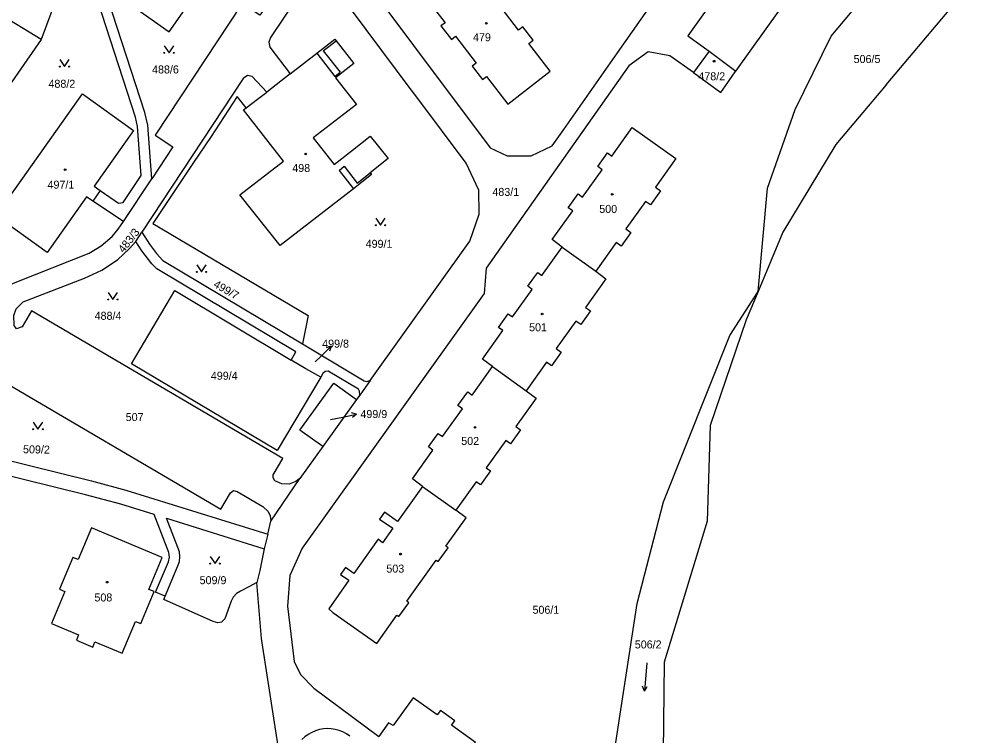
# Model space of a CAD drawing. Extents: x -558358 to -557517, y -1073786 to -1073189.
# Drawn here: x -558018.3 to -557815.7, y -1073559.5 to -1073407.2 of the extents above; entities that cross this region are included whole.
import ezdxf

# ---------------------------------------------------------------- set-up
doc = ezdxf.new("R2010")
doc.units = 0
for name, color, linetype in [('Hranice parcel', 7, 'Continuous'), ('Parcelní čísla', 7, 'Continuous'), ('Pop  PČ popisy', 7, 'Continuous'), ('Vnitřní kresba', 7, 'Continuous'), ('Značky budov', 7, 'Continuous'), ('Značky kultur', 7, 'Continuous')]:
    doc.layers.add(name, color=color, linetype=linetype)

msp = doc.modelspace()

# ---------------------------------------------------------------- linework, layer by layer
at = {"layer": 'Hranice parcel'}
for p, q in [((-557834.15, -1073421.11), (-557815.73, -1073399.27)), ((-558013.61, -1073411.49), (-558024.42, -1073404.91)), ((-558013.61, -1073411.49), (-558027.22, -1073431.17)), ((-557965.04, -1073413.14), (-557960.73, -1073418.81)), ((-557871.76, -1073413.96), (-557875.08, -1073418.52)), ((-557871.76, -1073413.96), (-557866.06, -1073418.25)), ((-557965.67, -1073422.67), (-557968.81, -1073419.39)), ((-557960.73, -1073418.81), (-557965.67, -1073422.67)), ((-557970.03, -1073426.04), (-557971.99, -1073423.64)), ((-557996.12, -1073450.19), (-557990.11, -1073441.11)), ((-558001.05, -1073443.62), (-558002.62, -1073445.83)), ((-558001.05, -1073443.62), (-557997.16, -1073446.28)), ((-557996.12, -1073450.19), (-558002.62, -1073445.83)), ((-557993.5, -1073454.4), (-557992.19, -1073452.45)), ((-557902.93, -1073455.63), (-557895.8, -1073460.74)), ((-557987.76, -1073458.45), (-557958.11, -1073476.19)), ((-557958.11, -1073476.19), (-557944.96, -1073484.06)), ((-557917.76, -1073481.02), (-557910.62, -1073486.13)), ((-557958.62, -1073494.5), (-557951.44, -1073484.51)), ((-557951.44, -1073484.51), (-557946.6, -1073487.99)), ((-557943.74, -1073483.99), (-557945.94, -1073487.07)), ((-557944.96, -1073484.06), (-557944.51, -1073484.17)), ((-557944.51, -1073484.17), (-557943.74, -1073483.99)), ((-557945.94, -1073487.07), (-557946.6, -1073487.99)), ((-557945.94, -1073487.07), (-557945.95, -1073486.25)), ((-557946.6, -1073487.99), (-557953.75, -1073497.99)), ((-557953.75, -1073497.99), (-557958.62, -1073494.5)), ((-557953.75, -1073497.99), (-557958.67, -1073504.77)), ((-557964.79, -1073513.87), (-557958.67, -1073504.77)), ((-557932.61, -1073506.45), (-557925.51, -1073511.53)), ((-557965.43, -1073516.64), (-557964.79, -1073513.87)), ((-557872.13, -1073513.82), (-557881.3, -1073543.83)), ((-557965.43, -1073516.64), (-557966.22, -1073519.7)), ((-557966.22, -1073519.7), (-557967.17, -1073524.31)), ((-557967.17, -1073524.31), (-557967.76, -1073526.9)), ((-557967.76, -1073526.9), (-557969.49, -1073527.78))]:
    msp.add_line(p, q, dxfattribs=at)
for points in [[(-558022.09, -1073311.21), (-558020.08, -1073313.87), (-558000.41, -1073328.2), (-557993.92, -1073334.5), (-557986.04, -1073343.93), (-557967.1, -1073369.2), (-557918.24, -1073434.51), (-557914.64, -1073436.24), (-557909.55, -1073436.22), (-557905.05, -1073434.1), (-557902.57, -1073430.65), (-557891.22, -1073414.37), (-557877.97, -1073395.43)], [(-557997.16, -1073446.28), (-557996.18, -1073446.14), (-557992.37, -1073440.37), (-557993.13, -1073429.99), (-557993.58, -1073428.02), (-558004.25, -1073395), (-558005.55, -1073391.58), (-558006.57, -1073389.94), (-558009.69, -1073386.81), (-558015.69, -1073381.13), (-558022.86, -1073375.1), (-558038.38, -1073364.54), (-558051.46, -1073355.75)], [(-557845.99, -1073372.93), (-557859.12, -1073391.15), (-557861.27, -1073389.6), (-557876.27, -1073410.74), (-557871.76, -1073413.96)], [(-557866.06, -1073418.25), (-557853.54, -1073400.64), (-557853.96, -1073400.34), (-557838.68, -1073378.19)], [(-558011.29, -1073387.48), (-558006.6, -1073392.58), (-558013.61, -1073411.49)], [(-557861.36, -1073465.07), (-557859.38, -1073443.12), (-557853.44, -1073426.35), (-557845.8, -1073410.81), (-557826.12, -1073387.26)], [(-557930.26, -1073400.48), (-557932.35, -1073402.1), (-557927.81, -1073407.96), (-557928.68, -1073408.63), (-557926.46, -1073411.51), (-557925.59, -1073410.83), (-557921.19, -1073416.52), (-557922.06, -1073417.2), (-557919.87, -1073420.02), (-557919, -1073419.35), (-557914.46, -1073425.22), (-557905.47, -1073418.2), (-557910.01, -1073412.34), (-557909.08, -1073411.62), (-557911.27, -1073408.79), (-557912.2, -1073409.51), (-557916.62, -1073403.8), (-557915.7, -1073403.08), (-557917.89, -1073400.24), (-557918.82, -1073400.96), (-557923.37, -1073395.09)], [(-557990.11, -1073441.11), (-557990.95, -1073429.72), (-557991.6, -1073426.99), (-558000.34, -1073399.97), (-557986.42, -1073409.86), (-557979.13, -1073399.38), (-557977.23, -1073400.7), (-557975.75, -1073398.59), (-557966.19, -1073404.96)], [(-557952.73, -1073399.73), (-557953.94, -1073399.59), (-557955.93, -1073399.82), (-557957.72, -1073400.8), (-557958.97, -1073402.15), (-557964.89, -1073411.09), (-557965.23, -1073412.1), (-557965.04, -1073413.14)], [(-557943.74, -1073483.99), (-557922.57, -1073454.37), (-557920.54, -1073448.62), (-557920.67, -1073443.5), (-557923.32, -1073437.76), (-557933.57, -1073424.07), (-557935, -1073422.19), (-557950.81, -1073400.97)], [(-557966.19, -1073404.96), (-557967.15, -1073406.3), (-557970.9, -1073403.86), (-557989.34, -1073431.82), (-557985.62, -1073434.28), (-557990.11, -1073441.11)], [(-557960.73, -1073418.81), (-557955.07, -1073414.41), (-557951.22, -1073411.42), (-557950.93, -1073411.8), (-557947.21, -1073416.59), (-557951.08, -1073419.63), (-557946.63, -1073425.3), (-557955.8, -1073432.39), (-557951.37, -1073438.08), (-557947.44, -1073435.04), (-557943.73, -1073432.04), (-557939.89, -1073436.78), (-557943.7, -1073439.86), (-557943.42, -1073440.21), (-557947.29, -1073443.23), (-557962.81, -1073455.3), (-557971.36, -1073444.52), (-557962.13, -1073437.38), (-557970.6, -1073426.47), (-557970.03, -1073426.04)], [(-557875.08, -1073418.52), (-557880.11, -1073415), (-557884.66, -1073414.11), (-557888.78, -1073417.07), (-557919.08, -1073460.09), (-557919.51, -1073465.45), (-557958.15, -1073519.56), (-557960.76, -1073525.37), (-557961.25, -1073531.9), (-557959.85, -1073543.64), (-557958.52, -1073546.41), (-557955.67, -1073549.33), (-557941.9, -1073559.58)], [(-557875.08, -1073418.52), (-557869.25, -1073422.74), (-557867.79, -1073420.61), (-557866.54, -1073418.89), (-557866.06, -1073418.25)], [(-557968.81, -1073419.39), (-557969.8, -1073419.14), (-557970.66, -1073419.77), (-557992.19, -1073452.45)], [(-557970.03, -1073426.04), (-557967.63, -1073424.2), (-557965.67, -1073422.67)], [(-557834.15, -1073421.11), (-557844.86, -1073433.81), (-557856.07, -1073452.41), (-557861.36, -1073465.07)], [(-558023.22, -1073448.98), (-558004.82, -1073423.06), (-557993.94, -1073430.83), (-558002.36, -1073442.69), (-558001.05, -1073443.62)], [(-557971.99, -1073423.64), (-557977.49, -1073432.15), (-557981.25, -1073437.64), (-557989.89, -1073450.63)], [(-557902.93, -1073455.63), (-557905.05, -1073454), (-557900.72, -1073447.94), (-557901.66, -1073447.27), (-557899.55, -1073444.33), (-557898.62, -1073444.99), (-557894.46, -1073439.18), (-557895.4, -1073438.51), (-557893.33, -1073435.61), (-557892.39, -1073436.28), (-557888.07, -1073430.23), (-557878.84, -1073436.82), (-557883.15, -1073442.9), (-557882.08, -1073443.65), (-557884.22, -1073446.66), (-557885.28, -1073445.91), (-557889.41, -1073451.73), (-557888.35, -1073452.48), (-557890.43, -1073455.41), (-557891.49, -1073454.66), (-557895.8, -1073460.74)], [(-558002.62, -1073445.83), (-558003.93, -1073444.91), (-558012.33, -1073456.75), (-558023.22, -1073448.98)], [(-558020.42, -1073463.73), (-558018.76, -1073463.03), (-558003.4, -1073456.89), (-558000.84, -1073455.32), (-557998.53, -1073453.34), (-557997.26, -1073451.83), (-557996.12, -1073450.19)], [(-557989.89, -1073450.63), (-557956.91, -1073470.13), (-557958.11, -1073476.19)], [(-557992.19, -1073452.45), (-557990.57, -1073454.98), (-557989.11, -1073456.98), (-557987.76, -1073458.45)], [(-558018.89, -1073468.72), (-558017.43, -1073467.28), (-558004.36, -1073462.2), (-558000.71, -1073460.54), (-557997.38, -1073458.33), (-557994.81, -1073455.9), (-557993.5, -1073454.4)], [(-557960.53, -1073479.61), (-557959.52, -1073477.88), (-557988.99, -1073460.22), (-557990.09, -1073459.14), (-557992.19, -1073456.42), (-557993.5, -1073454.4)], [(-557917.76, -1073481.02), (-557919.89, -1073479.42), (-557915.58, -1073473.37), (-557916.49, -1073472.72), (-557914.4, -1073469.79), (-557913.49, -1073470.44), (-557909.33, -1073464.6), (-557910.24, -1073463.95), (-557908.96, -1073462.17), (-557908.15, -1073461.02), (-557907.24, -1073461.67), (-557902.93, -1073455.63)], [(-557895.8, -1073460.74), (-557893.65, -1073462.39), (-557897.97, -1073468.43), (-557896.94, -1073469.17), (-557899.02, -1073472.08), (-557900.05, -1073471.34), (-557904.22, -1073477.17), (-557903.16, -1073477.93), (-557905.25, -1073480.84), (-557906.3, -1073480.09), (-557910.62, -1073486.13)], [(-557954.23, -1073483.22), (-557963.48, -1073498.87), (-557994.38, -1073480.4), (-557985.2, -1073464.81), (-557960.53, -1073479.61)], [(-557897.48, -1073592.57), (-557892.38, -1073566.43), (-557887.02, -1073531.37), (-557881.44, -1073509.74), (-557867.37, -1073474.4), (-557861.36, -1073465.07)], [(-557861.36, -1073465.07), (-557863.88, -1073471.1), (-557871.54, -1073493.51), (-557872.13, -1073513.82)], [(-557958.67, -1073504.77), (-557959.52, -1073505.42), (-557960.94, -1073505.97), (-557962.48, -1073505.9), (-557963.93, -1073505.3), (-557964.34, -1073504.64), (-557964.29, -1073503.98), (-557962.25, -1073500.52), (-558015.64, -1073469.14), (-558017.62, -1073472.56), (-558018.8, -1073472.98), (-558019.32, -1073472.29), (-558019.38, -1073470.18), (-558018.89, -1073468.72)], [(-558028.88, -1073478.68), (-558027.22, -1073477.58), (-558025.14, -1073477.37), (-558022.91, -1073477.77), (-558021.94, -1073478.27), (-558021.58, -1073478.9), (-558021.69, -1073479.54), (-558023.7, -1073482.95), (-557975.42, -1073511.29), (-557973.41, -1073507.84), (-557972.71, -1073507.36), (-557971.95, -1073507.53), (-557966.49, -1073510.72), (-557965.39, -1073511.77), (-557964.96, -1073512.7), (-557964.79, -1073513.87)], [(-557954.23, -1073483.22), (-557957.38, -1073481.46), (-557960.53, -1073479.61)], [(-557932.61, -1073506.45), (-557934.75, -1073504.84), (-557930.41, -1073498.76), (-557931.35, -1073498.09), (-557930.07, -1073496.31), (-557929.28, -1073495.19), (-557928.34, -1073495.86), (-557924.14, -1073489.96), (-557925.07, -1073489.3), (-557922.99, -1073486.39), (-557922.06, -1073487.05), (-557917.76, -1073481.02)], [(-557945.95, -1073486.25), (-557946.2, -1073485.81), (-557952.65, -1073481.96), (-557953.3, -1073482.07), (-557953.78, -1073482.47), (-557954.23, -1073483.22)], [(-557910.62, -1073486.13), (-557908.48, -1073487.72), (-557912.81, -1073493.77), (-557911.82, -1073494.47), (-557913.92, -1073497.39), (-557914.9, -1073496.69), (-557919.09, -1073502.55), (-557918.19, -1073503.19), (-557920.29, -1073506.11), (-557921.18, -1073505.47), (-557925.51, -1073511.53)], [(-558041.79, -1073496.35), (-558023.3, -1073500.28), (-558002.91, -1073505.27), (-557995.6, -1073507.26), (-557965.43, -1073516.64)], [(-557987.27, -1073529.77), (-557989.29, -1073528.94), (-557986.56, -1073522.48), (-557986.36, -1073521.52), (-557986.44, -1073520.51), (-557989.6, -1073512.4), (-557996.64, -1073510.25), (-558004.14, -1073508.22), (-558024.01, -1073503.35), (-558039.66, -1073500.03), (-558040.64, -1073500.03), (-558041.42, -1073500.4), (-558042.23, -1073501), (-558043.97, -1073502.01), (-558045.84, -1073502.74), (-558047.8, -1073503.22), (-558050.8, -1073503.37), (-558053.79, -1073503.03), (-558062.52, -1073500.9), (-558063.99, -1073500.68), (-558064.96, -1073500.91), (-558065.77, -1073501.48), (-558066.28, -1073502.33), (-558068.72, -1073511.63)], [(-557932.61, -1073506.45), (-557937.92, -1073513.94), (-557940.69, -1073511.97), (-557941.71, -1073513.4), (-557938.93, -1073515.37), (-557941.12, -1073518.46), (-557942.01, -1073517.7), (-557947.21, -1073524.97), (-557948.97, -1073523.73), (-557949.99, -1073525.17), (-557948.24, -1073526.41), (-557952.49, -1073532.47), (-557951.63, -1073533.27), (-557942.33, -1073539.86), (-557938.05, -1073533.83), (-557937.62, -1073534.14), (-557935.52, -1073531.19), (-557935.95, -1073530.88), (-557929.72, -1073522.11), (-557929.27, -1073522.43), (-557927.19, -1073519.5), (-557927.64, -1073519.19), (-557923.33, -1073513.13), (-557925.51, -1073511.53)], [(-557987.27, -1073529.77), (-557984.55, -1073523.36), (-557984.23, -1073522.42), (-557984.14, -1073521.45), (-557984.2, -1073520.39), (-557986.94, -1073513.23), (-557966.22, -1073519.7)], [(-558008.57, -1073528.8), (-558011.42, -1073535.59), (-558005.63, -1073538.02), (-558006.1, -1073539.13), (-558002.62, -1073540.59), (-558002.16, -1073539.49), (-557996.41, -1073541.91), (-557993.56, -1073535.14), (-557992.45, -1073535.6), (-557989.61, -1073528.81), (-557990.71, -1073528.34), (-557987.91, -1073521.54), (-558002.9, -1073515.24), (-558005.74, -1073522.02), (-558006.84, -1073521.56), (-558009.68, -1073528.33), (-558008.57, -1073528.8)], [(-557969.49, -1073527.78), (-557971.24, -1073528.71), (-557972.09, -1073529.24), (-557972.78, -1073529.97), (-557973.26, -1073530.86), (-557974.57, -1073534.63), (-557975.26, -1073535.31), (-557976.1, -1073535.45), (-557977.05, -1073535.17), (-557987.55, -1073530.47), (-557987.27, -1073529.77)], [(-557961.12, -1073576.24), (-557962.13, -1073568.62), (-557962.94, -1073563.5), (-557966.76, -1073538.79), (-557967.76, -1073526.9)], [(-557881.3, -1073543.83), (-557881.54, -1073569.39), (-557886.18, -1073582.51)], [(-557944.07, -1073562.64), (-557943.15, -1073563.3), (-557947.42, -1073569.28), (-557934.16, -1073578.7), (-557929.93, -1073572.77), (-557928.96, -1073573.46), (-557924.72, -1073567.52), (-557925.63, -1073566.74), (-557921.33, -1073560.9), (-557926.44, -1073557.23), (-557925.76, -1073556.27), (-557928.81, -1073554.08), (-557929.5, -1073555.03), (-557934.61, -1073551.36), (-557938.85, -1073557.29), (-557939.81, -1073556.68), (-557941.9, -1073559.58)], [(-557948.05, -1073559.56), (-557948.76, -1073559.06), (-557949.52, -1073558.64), (-557950.33, -1073558.32), (-557951.17, -1073558.09), (-557952.03, -1073557.96), (-557952.77, -1073557.92), (-557953.64, -1073557.97), (-557954.49, -1073558.12), (-557955.32, -1073558.37), (-557956.12, -1073558.72), (-557956.88, -1073559.15), (-557957.57, -1073559.67), (-557958.21, -1073560.26)]]:
    msp.add_lwpolyline(points, dxfattribs=at)
at = {"layer": 'Pop  PČ popisy'}
for p, q in [((-557954.15, -1073478.76), (-557951.99, -1073476.68)), ((-557951.99, -1073476.68), (-557953.06, -1073477.01)), ((-557951.99, -1073476.68), (-557952.36, -1073477.73)), ((-557955.41, -1073479.99), (-557954.15, -1073478.76)), ((-557949.53, -1073491.73), (-557946.59, -1073491.11)), ((-557946.59, -1073491.11), (-557947.68, -1073490.82)), ((-557946.59, -1073491.11), (-557947.47, -1073491.8)), ((-557952.15, -1073492.28), (-557949.53, -1073491.73))]:
    msp.add_line(p, q, dxfattribs=at)
at = {"layer": 'Vnitřní kresba'}
for p, q in [((-557953.7, -1073413.91), (-557950.93, -1073411.8)), ((-557955.07, -1073414.41), (-557951.25, -1073419.34)), ((-557953.7, -1073413.91), (-557950.12, -1073418.46)), ((-557951.25, -1073419.34), (-557950.12, -1073418.46)), ((-557950.33, -1073439.32), (-557949.26, -1073438.42)), ((-557949.26, -1073438.42), (-557946.5, -1073442)), ((-557950.33, -1073439.32), (-557947.29, -1073443.23)), ((-557946.5, -1073442), (-557943.7, -1073439.86))]:
    msp.add_line(p, q, dxfattribs=at)
at = {"layer": 'Značky budov'}
for centre in [(-557919.07, -1073408.06), (-557870.69, -1073416.12), (-557957.4, -1073435.82), (-558008.5, -1073439.16), (-557892.32, -1073444.4), (-557907.2, -1073469.84), (-557921.47, -1073493.92), (-557937.27, -1073520.85), (-557999.58, -1073526.81)]:
    msp.add_circle(centre, 0.175, dxfattribs=at)
at = {"layer": 'Značky kultur'}
for p, q in [((-557884.95, -1073543.96), (-557885.47, -1073549.94)), ((-557885.47, -1073549.94), (-557885.89, -1073548.92)), ((-557885.47, -1073549.94), (-557884.89, -1073549.01))]:
    msp.add_line(p, q, dxfattribs=at)
for points in [[(-557987.43, -1073412.84), (-557986.43, -1073414.34), (-557985.43, -1073412.84)], [(-558009.6, -1073415.75), (-558008.6, -1073417.25), (-558007.6, -1073415.75)], [(-557942.51, -1073449.49), (-557941.51, -1073450.99), (-557940.51, -1073449.49)], [(-557980.53, -1073459.39), (-557979.53, -1073460.89), (-557978.53, -1073459.39)], [(-557999.34, -1073465.25), (-557998.34, -1073466.75), (-557997.34, -1073465.25)], [(-558015.26, -1073492.81), (-558014.26, -1073494.31), (-558013.26, -1073492.81)], [(-557977.66, -1073521.36), (-557976.66, -1073522.86), (-557975.66, -1073521.36)]]:
    msp.add_lwpolyline(points, dxfattribs=at)
for centre in [(-557987.43, -1073414.34), (-557985.43, -1073414.34), (-558009.6, -1073417.25), (-558007.6, -1073417.25), (-557942.51, -1073450.99), (-557940.51, -1073450.99), (-557980.53, -1073460.89), (-557978.53, -1073460.89), (-557999.34, -1073466.75), (-557997.34, -1073466.75), (-558015.26, -1073494.31), (-558013.26, -1073494.31), (-557977.66, -1073522.86), (-557975.66, -1073522.86)]:
    msp.add_circle(centre, 0.1, dxfattribs=at)

# ---------------------------------------------------------------- texts
at = {"layer": 'Parcelní čísla'}
for s, p in [('479', (-557921.88, -1073411.88)), ('506/5', (-557841.06, -1073416.5)), ('488/6', (-557990.03, -1073418.72)), ('478/2', (-557874.03, -1073420.17)), ('488/2', (-558012.03, -1073421.76)), ('498', (-557960.26, -1073439.66)), ('497/1', (-558012.23, -1073443.2)), ('483/1', (-557917.77, -1073444.74)), ('500', (-557895.07, -1073448.35)), ('499/1', (-557944.68, -1073455.77)), ('488/4', (-558002.23, -1073471.06)), ('501', (-557909.97, -1073473.5)), ('499/8', (-557953.91, -1073476.98)), ('499/4', (-557977.55, -1073483.8)), ('507', (-557995.63, -1073492.58)), ('499/9', (-557945.79, -1073491.94)), ('502', (-557924.38, -1073497.65)), ('503', (-557940.28, -1073524.78)), ('509/9', (-557979.93, -1073527.24)), ('508', (-558002.27, -1073530.91)), ('506/1', (-557909.25, -1073533.53)), ('506/2', (-557887.53, -1073540.89))]:
    msp.add_text(s, height=1.7, dxfattribs=at).set_placement(p)
for s, rotation, p in [('483/3', 52, (-557996.07, -1073456.97)), ('499/7', 330, (-557977.15, -1073463.99)), ('509/2', 359, (-558017.44, -1073499.41))]:
    msp.add_text(s, height=1.7, rotation=rotation, dxfattribs=at).set_placement(p)

doc.saveas('drawing.dxf')
